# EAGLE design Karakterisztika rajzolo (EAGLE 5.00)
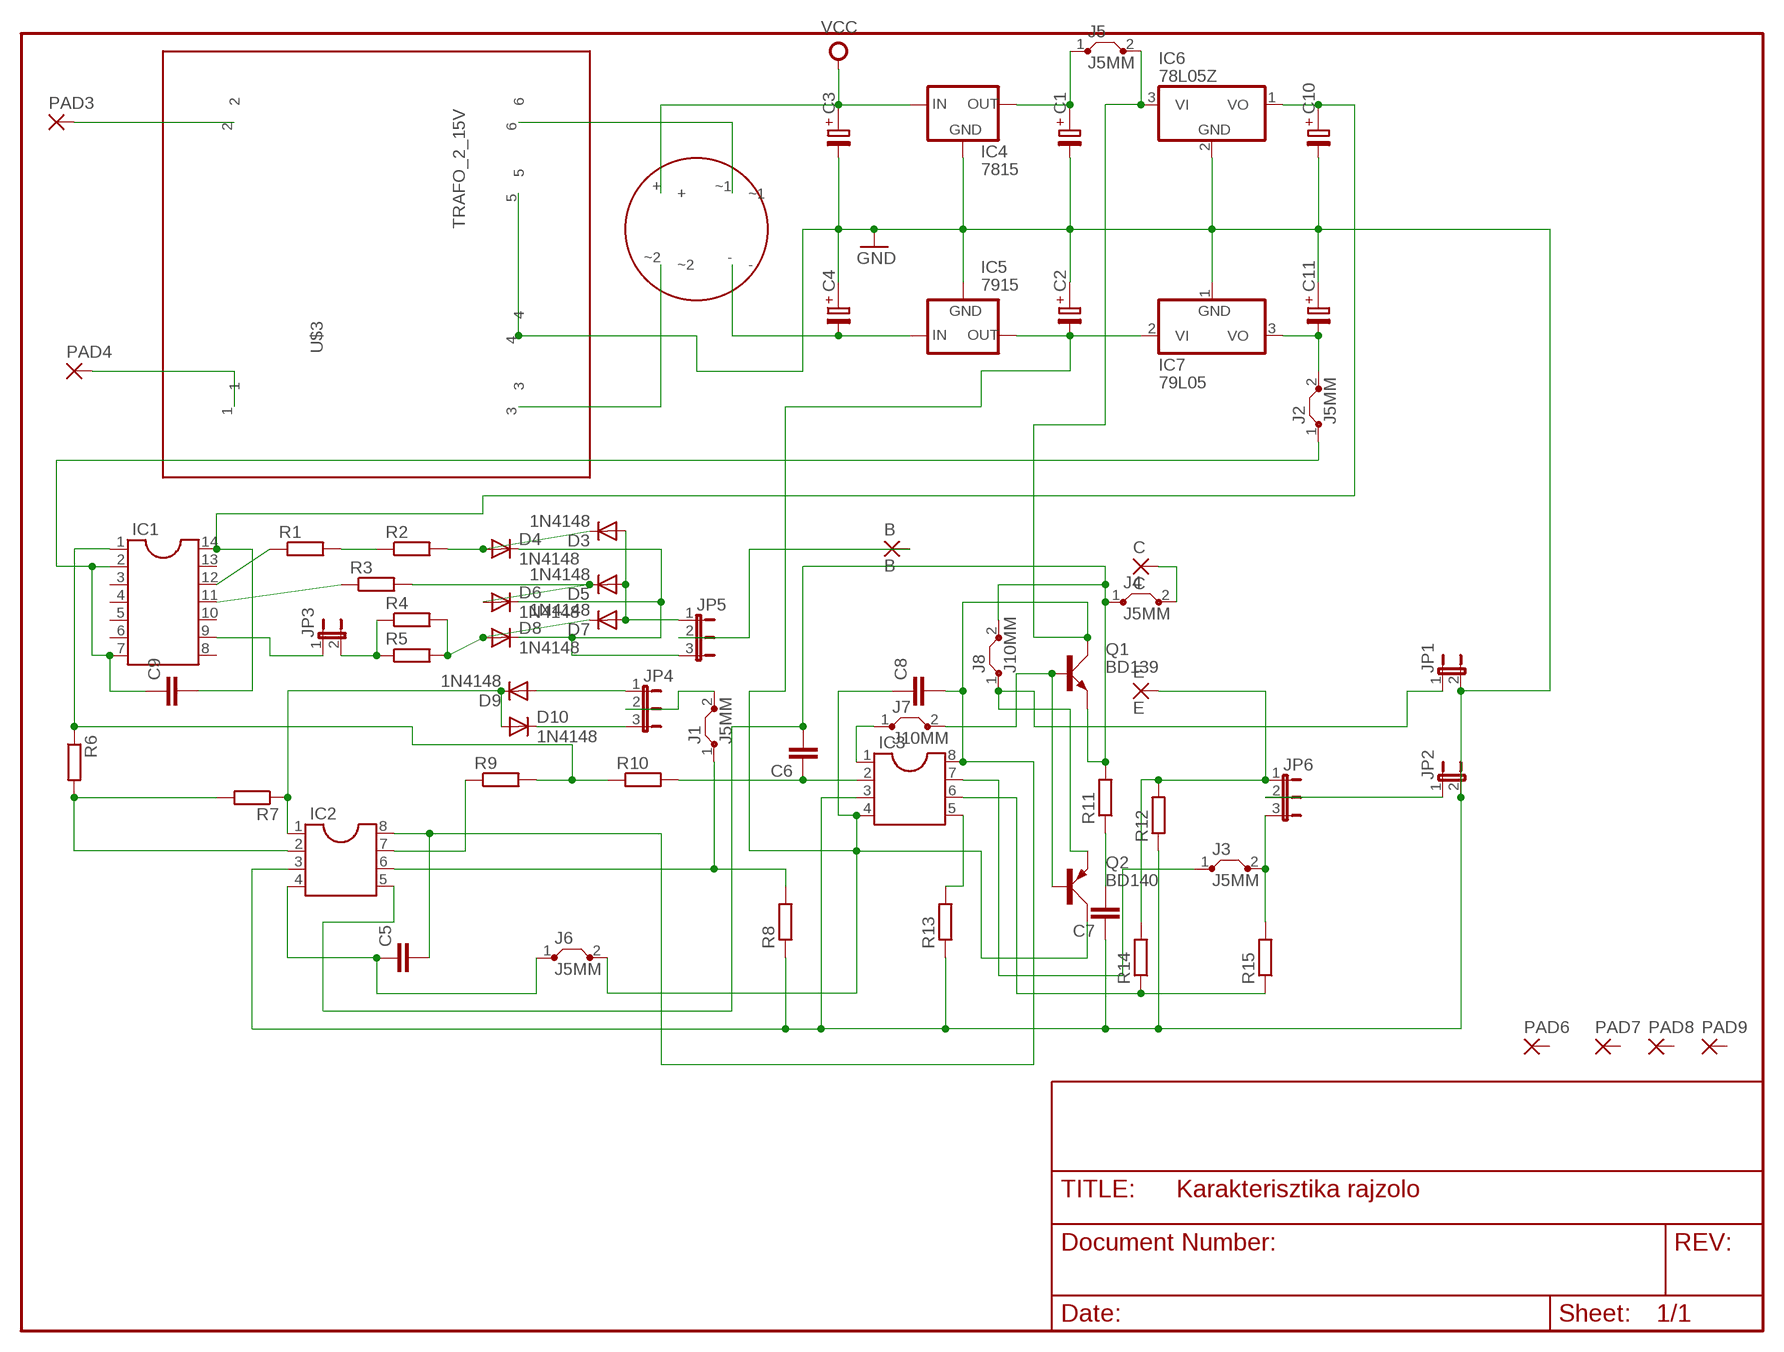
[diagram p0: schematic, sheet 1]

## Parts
B  B  2,54/1,0  [2,54/1,0]
C  C  2,54/1,0  [2,54/1,0]
C1  C-PR-5,0X10  [E5,0-10]
C2  C-PR-5,0X10  [E5,0-10]
C3  C-PR-5,0X10  [E5,0-10]
C4  C-PR-5,0X10  [E5,0-10]
C5  C-EU050-035X075  [C050-035X075]
C6  C-EU050-035X075  [C050-035X075]
C7  C-EU050-035X075  [C050-035X075]
C8  C-EU050-035X075  [C050-035X075]
C9  C-EU050-035X075  [C050-035X075]
C10  C-PR-5,0X10  [E5,0-10]
C11  C-PR-5,0X10  [E5,0-10]
D3  1N4148  [DO35-10]
D4  1N4148  [DO35-10]
D5  1N4148  [DO35-10]
D6  1N4148  [DO35-10]
D7  1N4148  [DO35-10]
D8  1N4148  [DO35-10]
D9  1N4148  [DO35-10]
D10  1N4148  [DO35-10]
E  E  2,54/1,0  [2,54/1,0]
IC1  DIL14  [DIL14]
IC2  DIL8  [DIL08]
IC3  DIL8  [DIL08]
IC4  7815  78MXXS  [78MXXS]
IC5  7915  79XXS  [79XXS]
IC6  78L05Z  [TO92]
IC7  79L05  79L05Z  [TO92]
J1  J5MM  [05]
J2  J5MM  [05]
J3  J5MM  [05]
J4  J5MM  [05]
J5  J5MM  [05]
J6  J5MM  [05]
J7  J10MM  [10]
J8  J10MM  [10]
JP1  JP1E  [JP1]
JP2  JP1E  [JP1]
JP3  JP1E  [JP1]
JP4  JP2E  [JP2]
JP5  JP2E  [JP2]
JP6  JP2E  [JP2]
PAD3  2,54/1,0  [2,54/1,0]
PAD4  2,54/1,0  [2,54/1,0]
PAD6  2,54/1,0  [2,54/1,0]
PAD7  2,54/1,0  [2,54/1,0]
PAD8  2,54/1,0  [2,54/1,0]
PAD9  2,54/1,0  [2,54/1,0]
Q1  BD139  [TO126AV]
Q2  BD140  [TO126AV]
R1  R-EU_0204/7  [0204/7]
R2  R-EU_0204/7  [0204/7]
R3  R-EU_0204/7  [0204/7]
R4  R-EU_0204/7  [0204/7]
R5  R-EU_0204/7  [0204/7]
R6  R-EU_0204/7  [0204/7]
R7  R-EU_0204/7  [0204/7]
R8  R-EU_0204/7  [0204/7]
R9  R-EU_0204/7  [0204/7]
R10  R-EU_0204/7  [0204/7]
R11  R-EU_0204/7  [0204/7]
R12  R-EU_0204/7  [0204/7]
R13  R-EU_0204/7  [0204/7]
R14  R-EU_0204/7  [0204/7]
R15  R-EU_0204/7  [0204/7]
U$3  TRAFO_2_15V  [TRAFO_2_15V]
U$4  B80C  [B80C]

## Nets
GND: C1.- C2.+ C3.- C4.+ C7.1 C10.- C11.+ IC2.3 IC3.3 IC4.GND IC5.GND IC6.2(GND) IC7.1(GND) JP1.2 JP2.2 R8.1 R12.1 R13.1 U$3.4 U$3.5
N$1: C5.2 C8.2 IC2.8 IC3.8 IC6.3(VI) J5.2 Q1.C
N$2: IC1.9 JP3.1
N$3: IC2.7 R9.1
N$4: J3.2 JP6.3 R15.2
N$5: C9.1 IC1.2 IC1.7 J2.1
N$6: IC1.12 R1.1
N$7: R1.2 R2.1
N$8: D3.C D4.A R2.2
N$9: IC1.11 R3.1
N$10: D5.C D6.A R3.2
N$11: D9.A JP4.1
N$12: JP2.1 JP6.2
N$13: D4.C D6.C D8.C JP5.3
N$14: D3.A D5.A D7.A JP5.1
N$15: D10.C JP4.3
N$16: IC1.1 R6.1 R9.2 R10.1
N$17: IC2.2 R6.2 R7.2
N$18: D9.C D10.A IC2.1 R7.1
N$19: C6.1 IC3.2 R10.2
N$20: IC2.6 J1.1 R8.2
N$21: PAD4.1(P) U$3.1
N$22: JP3.2 R4.1 R5.1
N$24: J1.2 JP4.2
N$25: PAD3.1(P) U$3.2
N$26: C7.2 R11.1
N$27: C11.- IC7.3(VO) J2.2
N$28: IC3.5 R13.2
N$29: B.1(P) JP5.2
N$30: C6.2 IC2.5 J4.1 J8.2 Q1.E R11.2
N$31: IC3.6 R14.1 R15.1
N$32: D7.C D8.A R4.2 R5.2
N$33: U$3.3 U$4.~2
N$34: U$3.6 U$4.~1
N$35: C5.1 IC2.4 J6.1
N$36: C9.2 C10.+ IC1.14 IC6.1(VO)
N$37: IC3.1 J7.1
N$38: C4.- IC5.IN U$4.-
N$39: C.1(P) J4.2
N$40: J7.2 Q1.B Q2.B
N$41: J8.1 JP1.1 Q2.E
N$42: IC3.7 J3.1
N$44: C2.- C8.1 IC3.4 IC5.OUT IC7.2(VI) J6.2 Q2.C
N$45: C1.+ IC4.OUT J5.1
N$46: E.1(P) JP6.1 R12.2 R14.2
VCC: C3.+ IC4.IN U$4.+
Unconnected: IC1.3 IC1.4 IC1.5 IC1.6 IC1.8 IC1.10 IC1.13 PAD6.1(P) PAD7.1(P) PAD8.1(P) PAD9.1(P)

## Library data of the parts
B C E PAD3 PAD4 PAD6-PAD9 = wirepad:2,54/1,0: THROUGH-HOLE PAD
C1-C4 C10 C11 = cap-pan40:C-PR: POLARIZED ELECTROLYTIC/TANTALUM
C5-C9 = rcl:C-EU: CAPACITOR, European symbol
D3-D10 = diode:1N4148: DIODE
IC1 = ic-package:DIL14: Dual In Line
IC2 IC3 = ic-package:DIL8: Dual In Line
IC4 = v-reg-2:78MXXS: VOLTAGE REGULATOR
IC5 = v-reg-2:79XXS: VOLTAGE REGULATOR
IC6 = linear:78*: Positive VOLTAGE REGULATOR Source: http://cache.national.com/ds/LM/LM78L05.pdf http://www.fairchildsemi.com/ds/LM/LM7805.pdf
IC7 = linear:79*: Negative VOLTAGE REGULATOR
J1-J8 = jumper:J: Bridge
JP1-JP3 = jumper:JP1E: JUMPER
JP4-JP6 = jumper:JP2E: JUMPER
Q1 = transistor-power:BD139: NPN TRANSISTOR
Q2 = transistor-power:BD140: PNP TRANSISTOR
R1-R15 = rcl:R-EU_: RESISTOR, European symbol
U$3 = trafo_2_15V:TRAFO_2_15V
U$4 = B80C:B80C

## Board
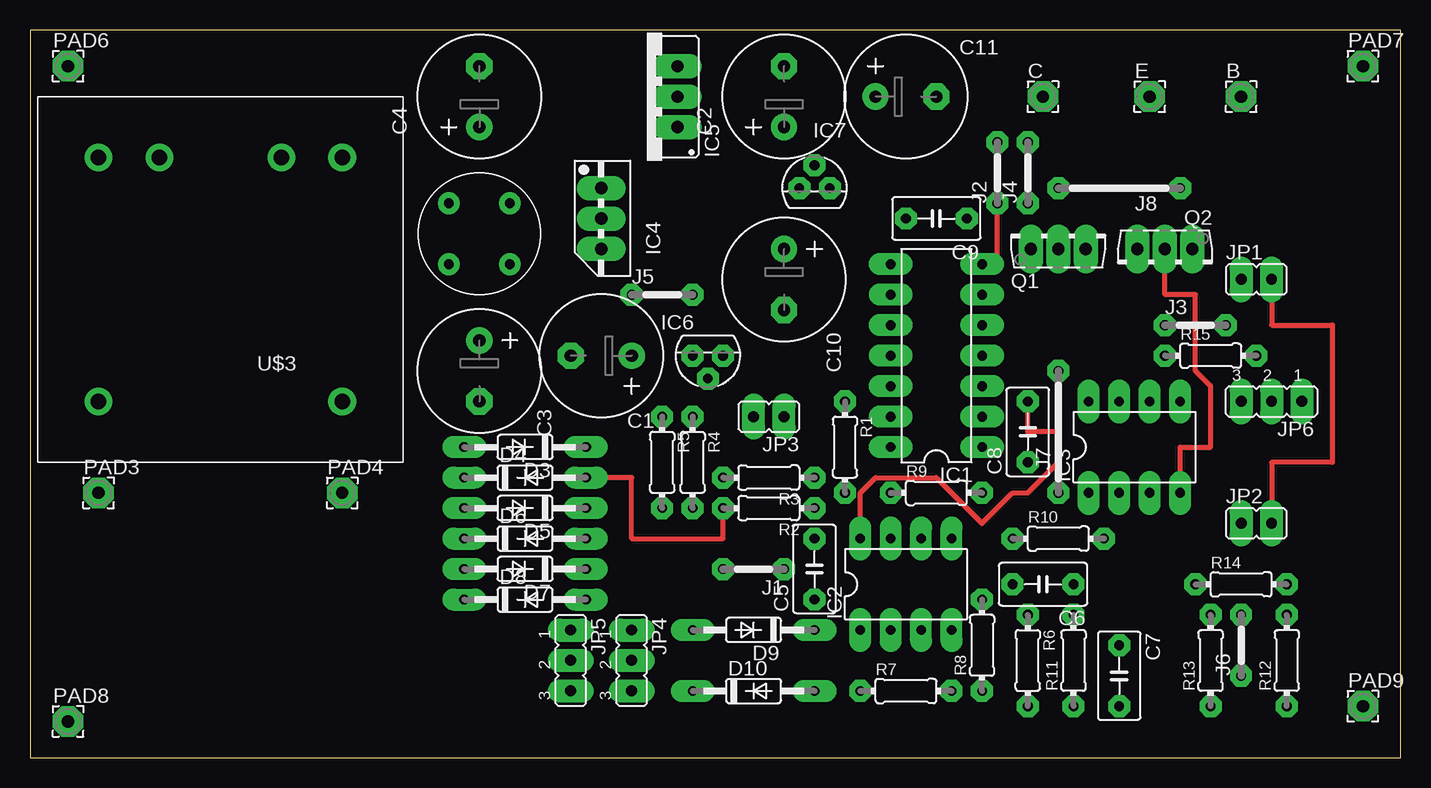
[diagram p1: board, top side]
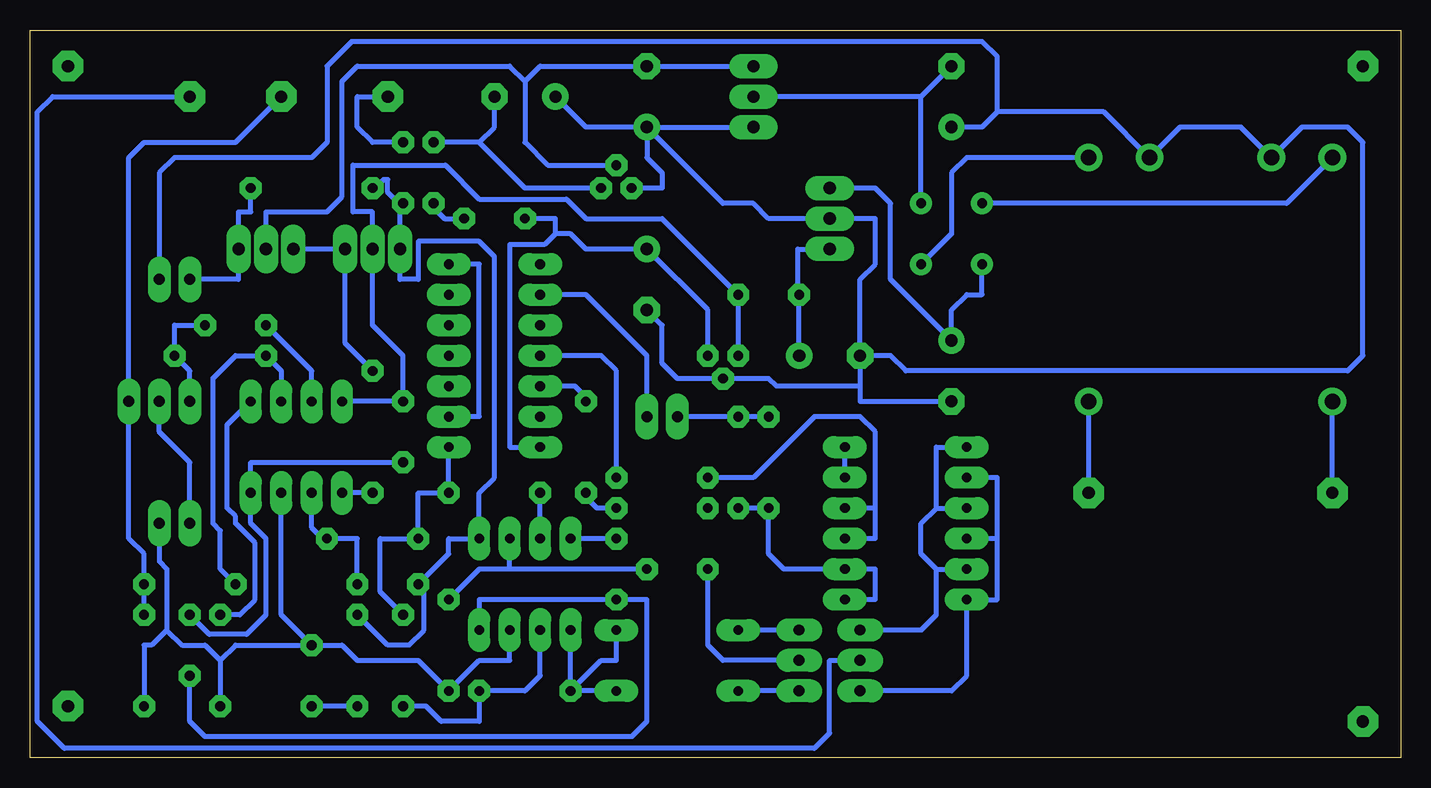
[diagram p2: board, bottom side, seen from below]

Size 114.28 x 60.63 mm. Coordinates in mm from the lower left corner, seen from the top.
Outline: 0,0 114.28,0 114.28,60.63 0,60.63 0,0
Copper layers (1*16): Top 0.035mm / dielectric 1.5mm / Bottom 0.035mm
Design rules "default": minimum track width 16mil, minimum drill 24mil, track to track 16mil, track to pad 16mil, pad to pad 16mil, via to via 16mil, smd to smd 8mil, copper to edge 40mil, drill to drill 16mil, minimum pad ring 20mil, minimum via ring 20mil, stop-mask expansion 4mil, vias tented up to drill 0mil, thermal gap 10mil

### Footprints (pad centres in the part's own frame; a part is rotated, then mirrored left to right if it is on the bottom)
2,54/1,0 = drill 1.016 pad 2.54 octagon: 1 0,0
E5,0-10 = drill 1.016 pad 2.184 round: + -2.54,0 | drill 1.016 pad 2.184 octagon: - 2.54,0
C050-035X075 = drill 0.813 octagon: 1 -2.54,0; 2 2.54,0
DO35-10 = drill 0.813 long: A 5.08,0; C -5.08,0
DIL14 = drill 0.813 long: 1 -7.62,-3.81; 2 -5.08,-3.81; 3 -2.54,-3.81; 4 0,-3.81; 5 2.54,-3.81; 6 5.08,-3.81; 7 7.62,-3.81; 8 7.62,3.81; 9 5.08,3.81; 10 2.54,3.81; 11 0,3.81; 12 -2.54,3.81; 13 -5.08,3.81; 14 -7.62,3.81
DIL08 = drill 0.813 long: 1 -3.81,-3.81; 2 -1.27,-3.81; 3 1.27,-3.81; 4 3.81,-3.81; 5 3.81,3.81; 6 1.27,3.81; 7 -1.27,3.81; 8 -3.81,3.81
78MXXS = drill 1.016 long: GND 0,-2.54; IN -2.54,-2.54; OUT 2.54,-2.54
79XXS = drill 1.016 long: GND -2.54,-2.54; IN 0,-2.54; OUT 2.54,-2.54
TO92 = drill 0.813 octagon: 1 -1.27,0; 2 0,1.905; 3 1.27,0
05 = drill 0.813 pad 1.6 octagon: 1 -2.54,0; 2 2.54,0
10 = drill 0.813 pad 1.6 octagon: 1 -5.08,0; 2 5.08,0
JP1 = drill 0.914 long: 1 0,-1.27; 2 0,1.27
JP2 = drill 0.914 long: 1 -2.54,0; 2 0,0; 3 2.54,0
TO126AV = drill 1.016 long: B 2.286,-1.27; C 0,-1.27; E -2.286,-1.27
0204/7 = drill 0.813 octagon: 1 -3.81,0; 2 3.81,0
TRAFO_2_15V = drill 1.3 round: 1 -10.16,10.16; 2 10.16,10.16; 3 -10.16,-10.16; 4 -5.08,-10.16; 5 5.08,-10.16; 6 10.16,-10.16
B80C = drill 0.8 round: + -2.54,2.54; - 2.54,-2.54; ~1 2.54,2.54; ~2 -2.54,-2.54

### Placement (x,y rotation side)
B  100.96,55.08 0 top
C  84.45,55.08 0 top
C1  47.62,33.49 180 top
C2  62.86,55.08 90 top
C3  37.46,32.22 270 top
C4  37.46,55.08 90 top
C5  65.4,15.71 90 top
C6  84.45,14.44 180 top
C7  90.8,6.82 270 top
C8  83.18,27.14 90 top
C9  75.56,44.92 180 top
C10  62.86,39.84 270 top
C11  73.02,55.08 0 top
D3  41.27,25.87 180 top
D4  41.27,23.33 0 top
D5  41.27,20.79 180 top
D6  41.27,18.25 0 top
D7  41.27,15.71 180 top
D8  41.27,13.17 0 top
D9  60.32,10.63 180 top
D10  60.32,5.55 0 top
E  93.34,55.08 0 top
IC1  75.56,33.49 90 top
IC2  73.02,14.44 0 top
IC3  92.07,25.87 0 top
IC4  50.16,44.92 270 top
IC5  51.43,55.08 90 top
IC6  56.51,33.49 180 top
IC7  65.4,47.46 0 top
J1  60.32,15.71 180 top
J2  80.64,48.73 90 top
J3  97.15,36.03 0 top
J4  83.18,48.73 90 top
J5  52.7,38.57 0 top
J6  100.96,9.36 90 top
J7  85.72,27.14 90 top
J8  90.8,47.46 180 top
JP1  102.23,39.84 270 top
JP2  102.23,19.52 270 top
JP3  61.59,28.41 90 top
JP4  50.16,8.09 270 top
JP5  45.08,8.09 270 top
JP6  103.5,29.68 180 top
PAD3  5.71,22.06 0 top
PAD4  26.03,22.06 0 top
PAD6  3.17,57.62 0 top
PAD7  111.12,57.62 0 top
PAD8  3.17,3.01 0 top
PAD9  111.12,4.28 0 top
Q1  85.72,43.65 0 top
Q2  94.61,41.11 180 top
R1  67.94,25.87 270 top
R2  61.59,20.79 180 top
R3  61.59,23.33 180 top
R4  55.24,24.6 270 top
R5  52.7,24.6 270 top
R6  83.18,8.09 270 top
R7  73.02,5.55 0 top
R8  79.37,9.36 90 top
R9  75.56,22.06 0 top
R10  85.72,18.25 0 top
R11  86.99,8.09 90 top
R12  104.77,8.09 90 top
R13  98.42,8.09 90 top
R14  100.96,14.44 0 top
R15  98.42,33.49 0 top
U$3  15.87,39.84 180 top
U$4  37.46,43.65 90 top

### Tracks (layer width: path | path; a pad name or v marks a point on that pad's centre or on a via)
GND
  Top 0.406: JP1.2 103.5,36.03 108.58,36.03 108.58,24.6 103.5,24.6 JP2.2
  Bottom 0.406: JP1.2 103.5,48.73 102.23,50 90.8,50 89.53,51.27 89.53,57.62 87.48,59.67 34.92,59.67 33.65,58.4 33.65,53.81 | 45.08,30.95 52.07,30.95 52.7,31.58 IC6.2 60.32,31.58 61.59,32.85 61.59,36.03 C10.- | C7.1 93.34,11.9 IC3.3 | 33.65,53.81 34.92,52.54 C4.+ | 45.08,30.95 45.08,29.68 C3.- | C1.- 42.54,33.49 41.27,32.22 4.44,32.22 3.17,33.49 3.17,51.27 4.44,52.54 8.25,52.54 U$3.5 13.33,52.54 18.41,52.54 U$3.4 24.76,53.81 33.65,53.81 | 102.86,10.63 102.86,15.71 103.5,16.34 JP2.2 | 102.86,10.63 104.13,9.36 104.77,9.36 R12.1 | C1.- 45.08,39.84 43.81,41.11 43.81,44.92 IC4.GND 52.7,44.92 53.97,46.19 56.51,46.19 C2.+ | C2.+ 67.94,52.54 C11.+ | C1.- 45.08,30.95 | C2.+ 62.86,50 61.59,48.73 61.59,47.46 IC7.1 | C7.1 88.26,9.36 86.99,8.09 81.91,8.09 R8.1 76.83,8.09 74.29,8.09 IC2.3 | C2.+ IC5.GND | C7.1 97.15,9.36 98.42,8.09 | 98.42,8.09 R13.1 | 98.42,8.09 99.69,9.36 101.59,9.36 102.86,10.63
N$1
  Top 0.406: C8.2 83.18,27.14 85.72,27.14 85.72,24.6 83.18,22.06 81.91,22.06 79.37,19.52 75.56,23.33 70.48,23.33 69.21,22.06 IC2.8
  Bottom 0.406: IC6.3 J5.2 61.59,44.92 67.94,44.92 69.57,46.55 76.83,46.55 79.65,49.37 87.35,49.37 87.35,45.48 85.72,45.48 Q1.C 85.72,36.03 83.18,33.49 C8.2 IC3.8 | C5.2 IC2.8
N$2
  Bottom 0.406: JP3.1 62.86,33.49 67.94,38.57 IC1.9
N$3
  Bottom 0.406: IC2.7 R9.1
N$4
  Bottom 0.406: J3.2 102.23,36.03 R15.2 100.96,32.22 JP6.3
N$5
  Top 0.406: J2.1 80.64,41.11 IC1.7
  Bottom 0.406: C9.1 79.73,44.92 80.64,45.83 J2.1 | IC1.7 76.83,41.11 76.83,28.41 IC1.2
N$6
  Bottom 0.406: IC1.12 68.85,30.95 67.94,30.04 R1.1
N$7
  Bottom 0.406: R1.2 67.94,21.7 67.03,20.79 R2.1
N$8
  Top 0.406: R2.2 57.78,18.25 50.16,18.25 50.16,23.33 D4.A
  Bottom 0.406: D4.A D3.C
N$9
  Bottom 0.406: IC1.11 66.67,33.49 65.4,32.22 R3.1
N$10
  Bottom 0.406: R3.2 53.97,23.33 48.89,28.41 45.08,28.41 43.81,27.14 43.81,20.79 | 43.81,20.79 43.81,18.25 D6.A | 43.81,20.79 D5.C
N$11
  Bottom 0.406: JP4.1 D9.A
N$12
  Bottom 0.406: JP6.2 103.5,27.14 100.96,24.6 JP2.1
N$13
  Bottom 0.406: 33.65,18.25 33.65,13.17 D8.C 36.19,6.82 37.46,5.55 JP5.3 | 33.65,18.25 33.65,23.33 D4.C | 33.65,18.25 D6.C
N$14
  Bottom 0.406: 38.73,20.79 38.73,25.87 D3.A | 38.73,15.71 40,16.98 40,19.52 38.73,20.79 | 38.73,15.71 38.73,11.9 40,10.63 JP5.1 | 38.73,20.79 D5.A | 38.73,15.71 D7.A
N$15
  Bottom 0.406: JP4.3 D10.C
N$16
  Bottom 0.406: R6.1 85.08,13.81 85.08,18.25 R10.1 81.91,22.06 R9.2 IC1.1
N$17
  Bottom 0.406: IC2.2 71.75,6.82 73.02,5.55 R7.2 76.83,3.01 80,3.01 81.27,4.28 R6.2
N$18
  Bottom 0.406: D10.A R7.1 | R7.1 66.67,8.09 65.4,8.09 D9.C | R7.1 IC2.1
N$19
  Bottom 0.406: C6.1 86.99,18.25 R10.2 89.89,18.25 90.8,19.16 IC3.2
N$20
  Bottom 0.406: R8.2 76.83,15.71 74.29,15.71 | J1.1 74.29,15.71 | 74.29,15.71 IC2.6
N$21
  Bottom 0.406: PAD4.1 U$3.1
N$22
  Bottom 0.406: JP3.2 R4.1 R5.1
N$24
  Bottom 0.406: J1.2 57.78,9.36 56.51,8.09 JP4.2
N$25
  Bottom 0.406: PAD3.1 U$3.2
N$26
  Bottom 0.406: R11.1 C7.2
N$27
  Bottom 0.406: 76.83,51.27 73.02,47.46 IC7.3 | 76.83,51.27 J2.2 | 76.83,51.27 75.56,52.54 C11.-
N$28
  Bottom 0.406: IC3.5 97.84,27.71 97.84,20.79 97.15,20.09 97.15,19.52 95.52,17.89 95.52,13.17 96.79,11.9 R13.2
N$29
  Bottom 0.406: B.1 112.39,55.08 113.66,53.81 113.66,3.01 111.42,0.77 48.89,0.77 47.62,2.04 47.62,8.09 JP5.2
N$30
  Bottom 0.406: J8.2 85.52,47.46 84.81,48.17 84.45,48.17 84.45,47.1 83.54,46.19 J4.1 83.43,45.94 Q1.E 83.43,39.84 81.91,39.84 81.91,43.02 76.83,43.02 75.56,41.74 75.56,23.33 76.83,22.06 IC2.5 79.37,18.25 79.37,16.98 C6.2 81.43,13.96 81.43,10.63 82.7,9.36 84.45,9.36 R11.2
N$31
  Bottom 0.406: R14.1 98.42,15.71 98.42,18.92 99.02,19.52 99.02,31.62 97.15,33.49 R15.1 93.34,32.22 IC3.6
N$32
  Bottom 0.406: D8.A 43.81,13.17 43.81,15.71 D7.C 51.43,15.71 52.7,16.98 R5.2 R4.2
N$33
  Bottom 0.406: U$4.~2 37.46,43.65 37.46,48.73 36.19,50 U$3.3
N$34
  Bottom 0.406: U$3.6 9.52,46.19 U$4.~1
N$35
  Bottom 0.406: J6.1 100.96,3.01 99.69,1.74 64.13,1.74 62.86,3.01 62.86,13.17 C5.1 76.83,13.17 IC2.4
N$36
  Bottom 0.406: 70.48,43.65 71.39,42.74 74.29,42.74 74.29,25.87 IC1.14 | 70.48,43.65 70.48,44.92 C9.2 | IC6.1 57.78,37.3 C10.+ 67.94,42.38 69.21,43.65 70.48,43.65
N$37
  Bottom 0.406: J7.1 IC3.1
N$38
  Bottom 0.406: 40,55.08 IC5.IN | U$4.- 40,55.08 | 40,55.08 C4.-
N$39
  Bottom 0.406: C.1 86.99,55.08 86.99,52.54 85.72,51.27 J4.2
N$40
  Bottom 0.406: Q2.B Q1.B 88.01,34.51 J7.2
N$41
  Bottom 0.406: JP1.1 96.9,39.84 Q2.E 96.9,45.48 95.88,45.48 J8.1
N$42
  Bottom 0.406: J3.1 90.8,32.22 IC3.7
N$44
  Top 0.406: Q2.C 94.61,38.57 97.15,38.57 97.15,32.22 98.42,30.95 98.42,25.87 95.88,25.87 IC3.4
  Bottom 0.406: C8.1 95.88,24.6 IC3.4 95.88,19.52 94.61,18.25 94.61,11.9 96.24,10.27 99.33,10.27 J6.2 | Q2.C 94.61,45.48 89.53,45.48 88.26,46.75 88.26,56.35 86.99,57.62 74.29,57.62 73.02,56.35 | 73.02,56.35 73.02,51.27 71.11,49.37 IC7.2 | 73.02,56.35 71.75,57.62 C2.- IC5.OUT
N$45
  Bottom 0.406: C1.+ J5.1 50.26,38.67 50.26,42.38 IC4.OUT
N$46
  Bottom 0.406: E.1 97.15,51.27 104.77,51.27 106.04,50 JP6.1 106.04,18.25 104.77,16.98 R14.2 R12.2
VCC
  Bottom 0.406: IC4.IN 43.81,47.46 42.54,46.19 42.54,39.84 C3.+ 37.46,37.3 36.19,38.57 34.92,38.57 U$4.+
